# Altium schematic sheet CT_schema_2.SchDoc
size 287 x 169 mm
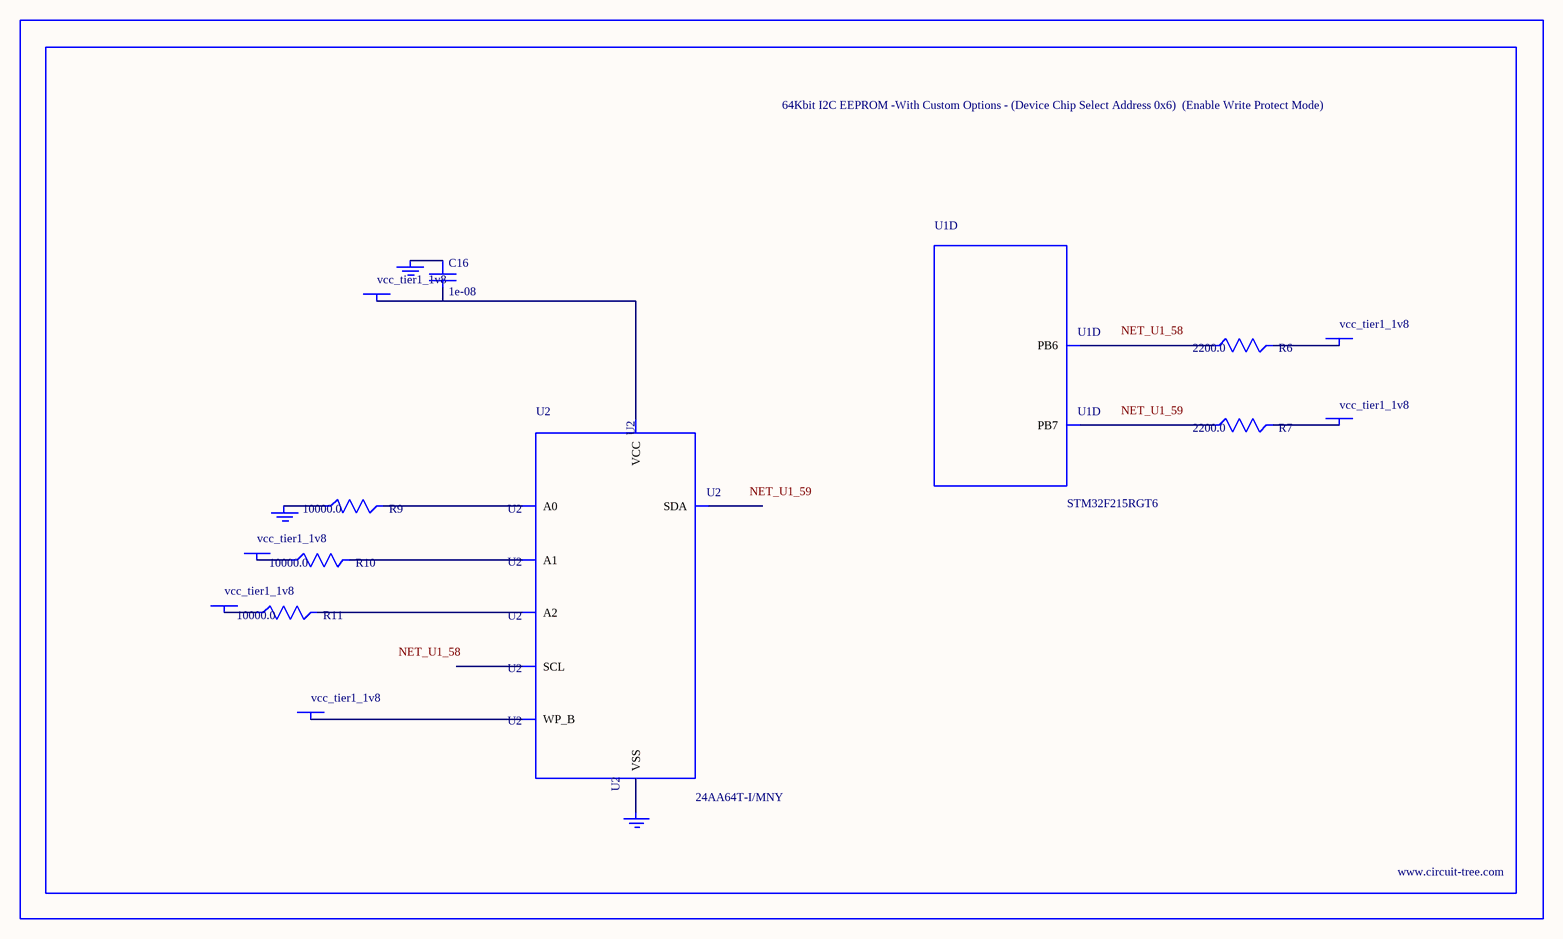
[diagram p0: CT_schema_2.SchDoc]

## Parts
BORDER1  (no value)
C16  1e-08  [C0402]
GND_INSTANCE_1_0  (no value)
GND_INSTANCE_1_1  (no value)
GND_INSTANCE_1_2  (no value)
POWER_INSTANCE_1_0  vcc_tier1_1v8
POWER_INSTANCE_1_1  vcc_tier1_1v8
POWER_INSTANCE_1_2  vcc_tier1_1v8
POWER_INSTANCE_1_3  vcc_tier1_1v8
POWER_INSTANCE_1_4  vcc_tier1_1v8
POWER_INSTANCE_1_5  vcc_tier1_1v8
R6  2200.0  [R0603]
R7  2200.0  [R0603]
R9  10000.0  [R0603]
R10  10000.0  [R0603]
R11  10000.0  [R0603]
U1  STM32F215RGT6  [LQFP64]  (part D of 7)
U2  24AA64T-I/MNY  [TDFN-8/6MM]

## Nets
NetC16_1: C16.1 GND_INSTANCE_1_1.0(GND)
NetC16_2: C16.2 POWER_INSTANCE_1_3.0(PWR) U2.8(VCC)
NetGND_INSTANCE_1_0_0: GND_INSTANCE_1_0.0(GND) R9.1
NetGND_INSTANCE_1_2_0: GND_INSTANCE_1_2.0(GND) U2.4(VSS)
NetPOWER_INSTANCE_1_0_0: POWER_INSTANCE_1_0.0(PWR) R10.1
NetPOWER_INSTANCE_1_1_0: POWER_INSTANCE_1_1.0(PWR) R11.1
NetPOWER_INSTANCE_1_2_0: POWER_INSTANCE_1_2.0(PWR) U2.7(WP_B)
NetPOWER_INSTANCE_1_4_0: POWER_INSTANCE_1_4.0(PWR) R6.2
NetPOWER_INSTANCE_1_5_0: POWER_INSTANCE_1_5.0(PWR) R7.2
NetR6_1: R6.1 U1.58(PB6)
NetR7_1: R7.1 U1.59(PB7)
NetR9_2: R9.2 U2.1(A0)
NetR10_2: R10.2 U2.2(A1)
NetR11_2: R11.2 U2.3(A2)

Not connected (* = marked no-connect by the designer): U2 5(SDA) 6(SCL)

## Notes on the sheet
- Labels drawn without touching a wire or pin: NET_U1_58, NET_U1_59

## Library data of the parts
BORDER1 = BORDER_PAGE1
C16 = C0402C103K3RAC
GND_INSTANCE_1_0-GND_INSTANCE_1_2 = GND
POWER_INSTANCE_1_0-POWER_INSTANCE_1_5 = PWR
R6 R7 = RC0603JR-072K2L
R9-R11 = RC0603JR-0710KL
